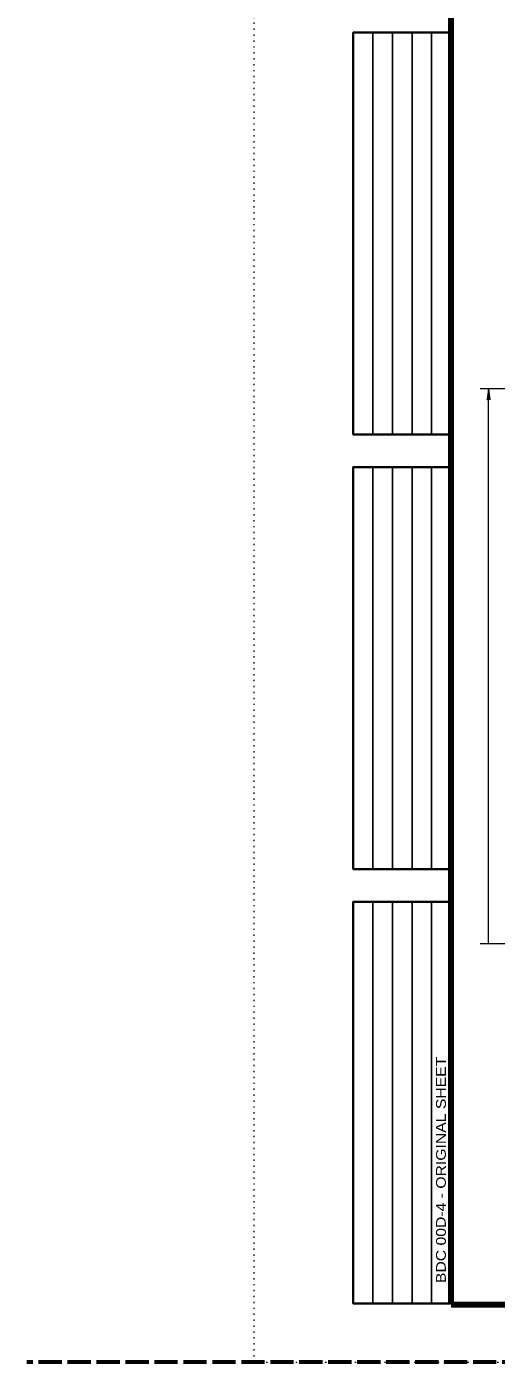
# Model space of a CAD drawing. Extents: x 312583 to 312854, y 144419 to 144597.
# Drawn here: x 312583.5 to 312620, y 144418.6 to 144522.3 of the extents above; entities that cross this region are included whole.
import ezdxf

# ---------------------------------------------------------------- set-up
doc = ezdxf.new("R2010")
doc.units = 0
doc.header["$LTSCALE"] = 0.3
doc.linetypes.add('DOTTED', pattern=[1.5, 0.3, -1.2])
doc.linetypes.add('LONG_DASHED', pattern=[7.5, 6, -1.5])
for name, color, linetype, lineweight in [('1', 7, 'Continuous', 25), ('2', 7, 'Continuous', 13), ('63', 7, 'DOTTED', 13)]:
    doc.layers.add(name, color=color, linetype=linetype, lineweight=lineweight)

msp = doc.modelspace()

# ---------------------------------------------------------------- linework, layer by layer
at = {"layer": '1'}
for p, q in [((312610.4087, 144490.6573), (312610.4087, 144521.8756)), ((312611.9315, 144490.6573), (312611.9315, 144521.8756)), ((312613.4543, 144490.6573), (312613.4543, 144521.8756)), ((312614.9772, 144490.6573), (312614.9772, 144521.8756)), ((312610.4087, 144456.901), (312610.4087, 144488.1192)), ((312611.9315, 144456.901), (312611.9315, 144488.1192)), ((312613.4543, 144456.901), (312613.4543, 144488.1192)), ((312614.9772, 144456.901), (312614.9772, 144488.1192)), ((312610.4087, 144423.1446), (312610.4087, 144454.3629)), ((312611.9315, 144423.1446), (312611.9315, 144454.3629)), ((312613.4543, 144423.1446), (312613.4543, 144454.3629)), ((312614.9772, 144423.1446), (312614.9772, 144454.3629))]:
    msp.add_line(p, q, dxfattribs=at)
at = {"layer": '1', "lineweight": 158}
msp.add_line((312616.5, 144423.0846), (312849, 144423.0846), dxfattribs=at)
at = {"layer": '1', "linetype": 'LONG_DASHED', "lineweight": 60}
msp.add_line((312851.75, 144418.5846), (312583.526, 144418.5846), dxfattribs=at)
at = {"layer": '1', "lineweight": 158}
msp.add_lwpolyline([(312616.5, 144423.1446), (312616.5, 144585.0846), (312849, 144585.0846)], dxfattribs=at)
at = {"layer": '1', "lineweight": 35}
for points in [[(312616.5, 144490.6573), (312608.8858, 144490.6573), (312608.8858, 144521.8756), (312616.5, 144521.8756)], [(312616.5, 144456.901), (312608.8858, 144456.901), (312608.8858, 144488.1192), (312616.5, 144488.1192)], [(312616.5, 144423.1446), (312608.8858, 144423.1446), (312608.8858, 144454.3629), (312616.5, 144454.3629)]]:
    msp.add_lwpolyline(points, dxfattribs=at)
at = {"layer": '2'}
for p, q in [((312625.8125, 144494.2114), (312618.7438, 144494.2114)), ((312619.3878, 144494.2114), (312619.2805, 144493.3451)), ((312619.3878, 144494.2114), (312619.4951, 144493.3451)), ((312619.3878, 144451.0864), (312619.3878, 144494.2114)), ((312619.2805, 144493.3451), (312619.3878, 144493.6211)), ((312619.4951, 144493.3451), (312619.3878, 144493.6211)), ((312625.6975, 144451.0864), (312618.7438, 144451.0864))]:
    msp.add_line(p, q, dxfattribs=at)
at = {"layer": '63'}
msp.add_line((312601.2, 144418.5846), (312601.2, 144596.7846), dxfattribs=at)
msp.add_lwpolyline([(312601.2, 144418.5846), (312853.5, 144418.5846), (312853.5, 144596.7846)], dxfattribs=at)

# ---------------------------------------------------------------- texts
at = {"layer": '1', "width": 1.2}
msp.add_text('BDC 00D-4 - ORIGINAL SHEET', height=0.7614, rotation=90, dxfattribs=at).set_placement((312616.0832, 144424.7374))

doc.saveas('drawing.dxf')
